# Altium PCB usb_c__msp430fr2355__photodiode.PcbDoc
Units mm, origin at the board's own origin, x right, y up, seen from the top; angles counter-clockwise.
Board outline 56 x 30 mm, 2 copper layers (Top, Bottom), stack 0 mm thick; 27 components, 18 nets, 154 pads, 44 vias.
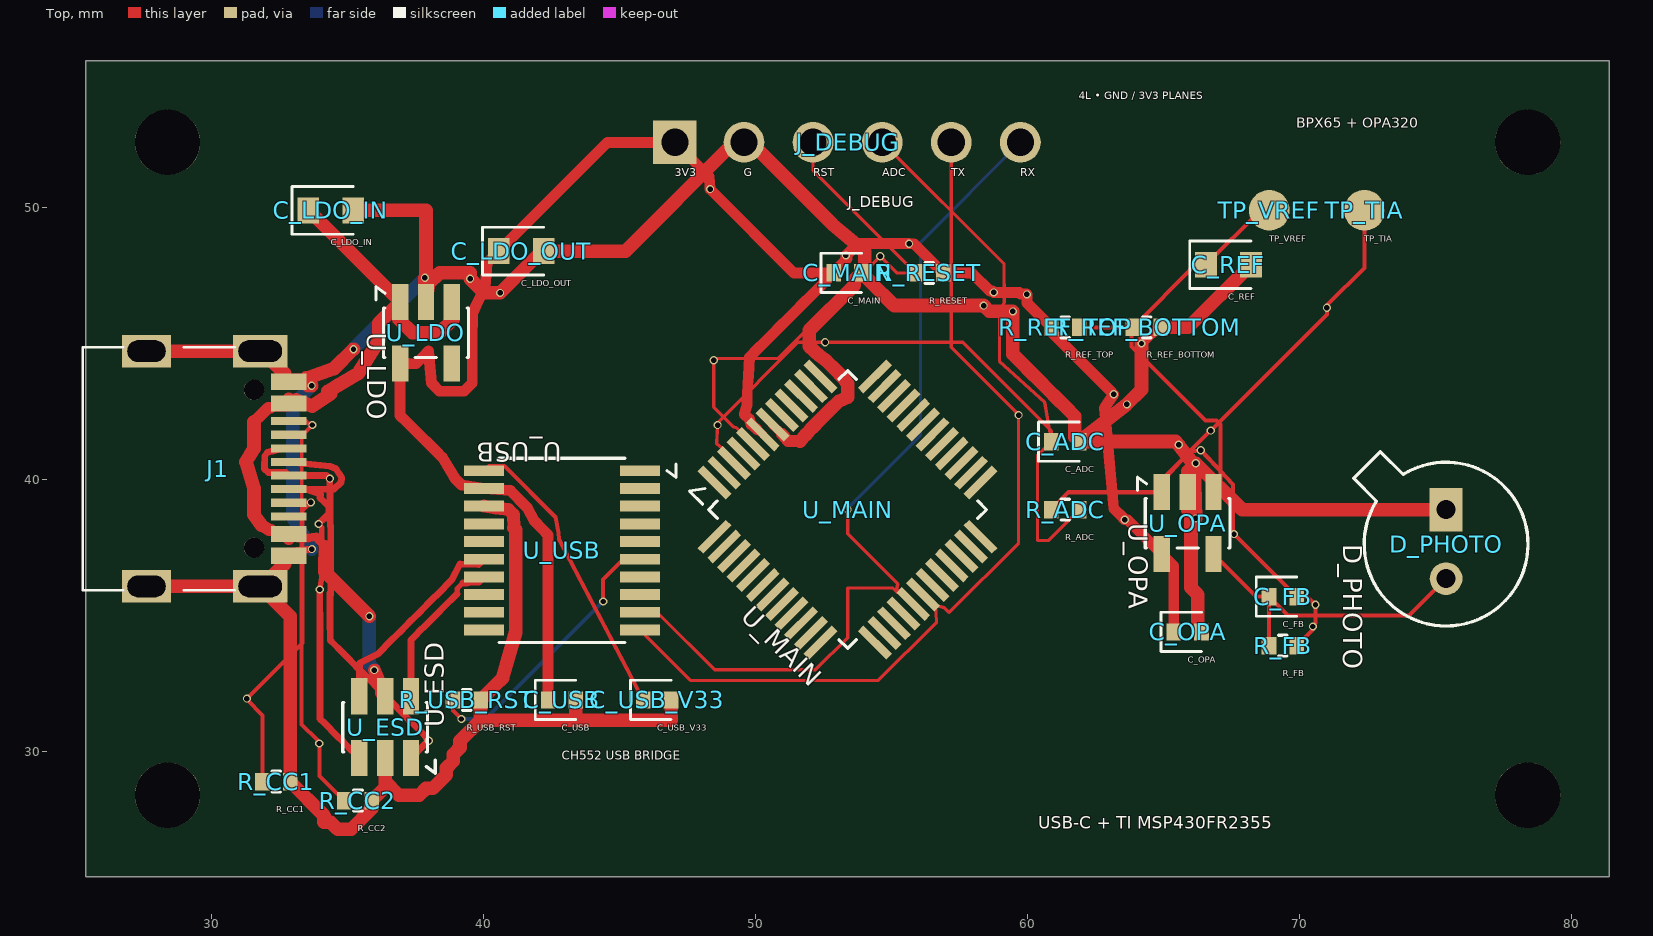
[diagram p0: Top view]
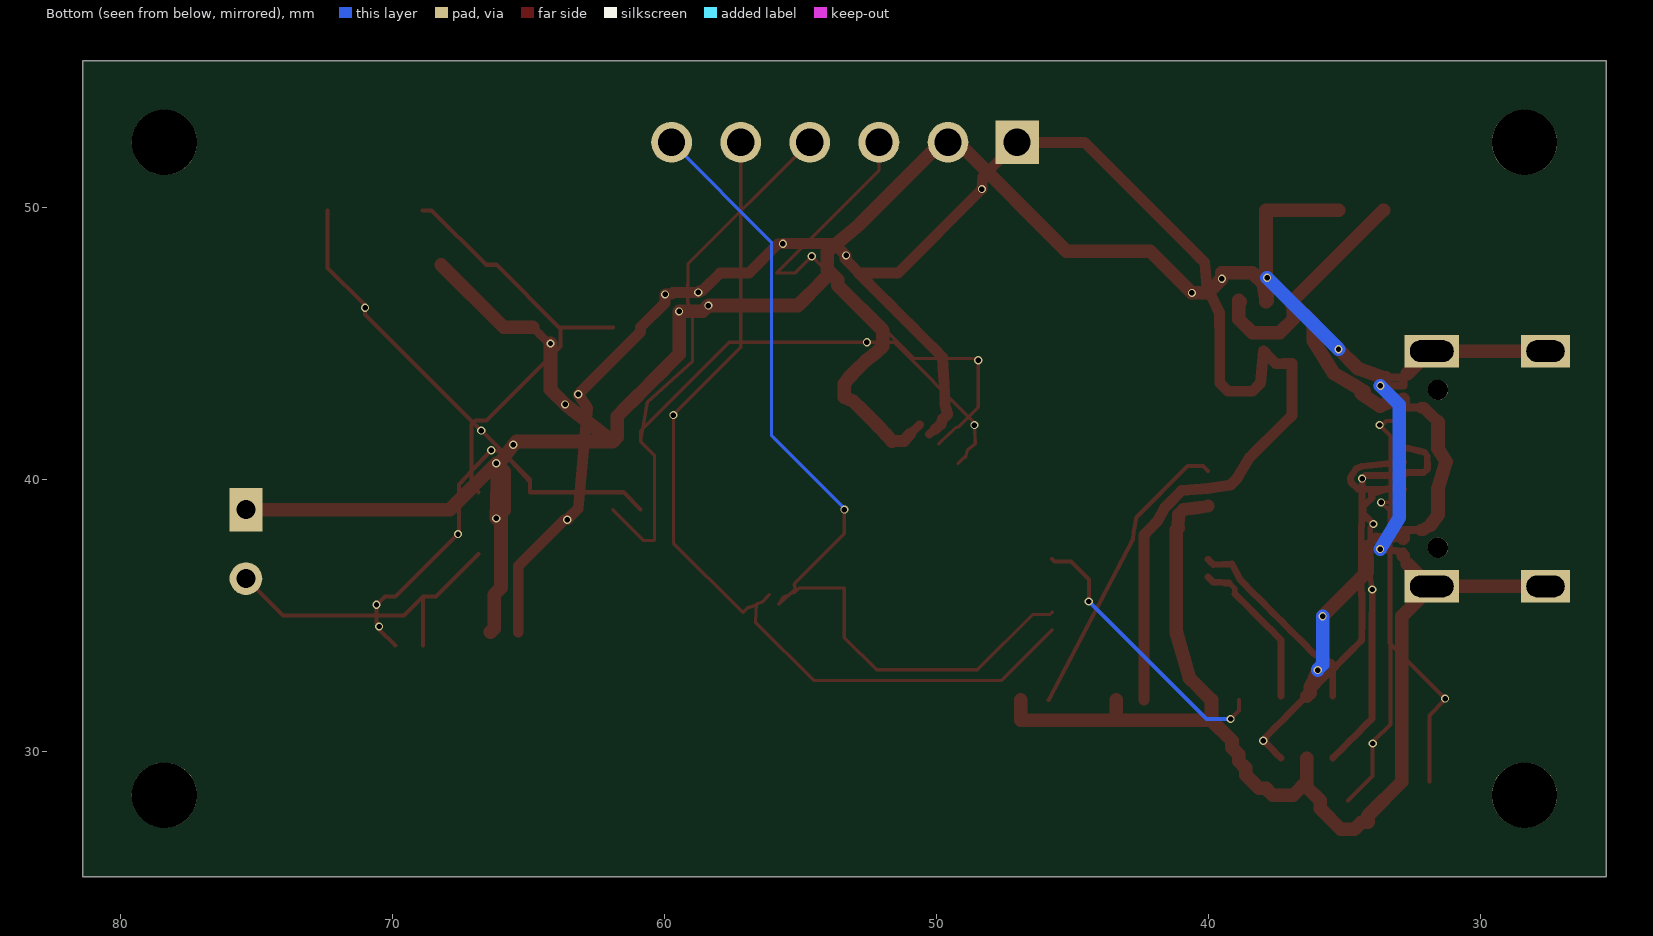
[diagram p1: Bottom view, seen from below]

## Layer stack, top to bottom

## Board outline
25.4,55.4 81.4,55.4 81.4,25.4 25.4,25.4

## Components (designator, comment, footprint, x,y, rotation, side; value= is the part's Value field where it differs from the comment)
C_ADC "" TSCIRCUIT-1.5600x0.6400mm 61.4,41.4 r0 top
C_FB "" TSCIRCUIT-1.5600x0.6400mm 69.4,35.7 r0 top
C_LDO_IN "" TSCIRCUIT-2.4500x0.9500mm 34.4,49.9 r0 top
C_LDO_OUT "" TSCIRCUIT-2.4500x0.9500mm 41.4,48.4 r0 top
C_MAIN "" TSCIRCUIT-1.5600x0.6400mm 53.4,47.6 r0 top
C_OPA "" TSCIRCUIT-1.5600x0.6400mm 65.9,34.4 r0 top
C_REF "" TSCIRCUIT-2.4500x0.9500mm 67.4,47.9 r0 top
C_USB "" TSCIRCUIT-1.5600x0.6400mm 42.9,31.9 r0 top
C_USB_V33 "" TSCIRCUIT-1.5600x0.6400mm 46.4,31.9 r0 top
D_PHOTO "" TSCIRCUIT-1.2000x3.9400mm 75.4,37.73 r270 top
J1 "" TSCIRCUIT-6.7732x9.8502mm 30.113,40.4 r90 top
J_DEBUG "" TSCIRCUIT-14.2000x1.5000mm 53.4,52.4 r0 top
R_ADC "" TSCIRCUIT-1.5600x0.6400mm 61.4,38.9 r0 top
R_CC1 "" TSCIRCUIT-1.5600x0.6400mm 32.4,28.9 r0 top
R_CC2 "" TSCIRCUIT-1.5600x0.6400mm 35.4,28.2 r0 top
R_FB "" TSCIRCUIT-1.5600x0.6400mm 69.4,33.9 r0 top
R_REF_BOTTOM "" TSCIRCUIT-1.5600x0.6400mm 64.4,45.6 r0 top
R_REF_TOP "" TSCIRCUIT-1.5600x0.6400mm 61.4,45.6 r0 top
R_RESET "" TSCIRCUIT-1.5600x0.6400mm 56.4,47.6 r0 top
R_USB_RST "" TSCIRCUIT-1.5600x0.6400mm 39.4,31.9 r0 top
TP_TIA "" TSCIRCUIT-1.5000x1.5000mm 72.4,49.9 r0 top
TP_VREF "" TSCIRCUIT-1.5000x1.5000mm 68.9,49.9 r0 top
U_ESD "" TSCIRCUIT-2.5000x3.6000mm#1 36.4,30.9 r90 top
U_LDO "" TSCIRCUIT-2.5000x3.6000mm#2 37.9,45.4 r270 top
U_MAIN "" TSCIRCUIT-11.0309x11.0309mm 53.4,38.9 r315 top
U_OPA "" TSCIRCUIT-2.5000x3.6000mm#2 65.9,38.4 r270 top
U_USB "" TSCIRCUIT-7.2000x6.2500mm 42.9,37.4 r180 top

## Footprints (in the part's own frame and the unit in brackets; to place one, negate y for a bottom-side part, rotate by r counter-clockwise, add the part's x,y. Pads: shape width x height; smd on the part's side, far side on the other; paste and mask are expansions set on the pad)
TSCIRCUIT-1.2000x3.9400mm [mm]
  rect 1.6x1.2 hole 0.7: 1(-1.17,0)
  round 1.2 hole 0.7: 2(1.37,0)
  silkscreen extent -3.3,-3.4 3.11,3.01
TSCIRCUIT-1.5000x1.5000mm [mm]
  round 1.5 smd: 1(0,0)
TSCIRCUIT-1.5600x0.6400mm [mm]
  rect 0.54x0.64 smd: 1(-0.51,0) 2(0.51,0)
  silkscreen extent -0.98,-0.72 0.51,0.72
TSCIRCUIT-2.4500x0.9500mm [mm]
  rect 0.8x0.95 smd: 1(-0.825,0) 2(0.825,0)
  silkscreen extent -1.43,-0.87 0.82,0.87
TSCIRCUIT-2.5000x3.6000mm#1 [mm]
  rect 1.325x0.6 smd: 1(-1.137,-0.95) 2(-1.137,0) 3(-1.137,0.95) 4(1.138,0.95) 5(1.138,0) 6(1.138,-0.95)
  silkscreen extent -1.69,-1.84 0.91,1.56
TSCIRCUIT-2.5000x3.6000mm#2 [mm]
  rect 1.325x0.6 smd: 1(-1.137,-0.95) 2(-1.137,0) 3(-1.137,0.95) 4(1.138,0.95) 5(1.138,-0.95)
  silkscreen extent -1.69,-1.84 0.91,1.56
TSCIRCUIT-6.7732x9.8502mm [mm]
  rect 0.3x1.3 smd: 1(-3.35,-2.737) 2(-3.05,-2.737) 3(-2.55,-2.737) 4(-2.25,-2.737) 5(-1.75,-2.737) 6(-1.25,-2.737) 7(-0.75,-2.737) 8(-0.25,-2.737) 9(0.25,-2.737) 10(0.75,-2.737) 11(1.25,-2.737) 12(1.75,-2.737) 13(2.55,-2.737) 14(2.25,-2.737) 15(3.35,-2.737) 16(3.05,-2.737)
  rect 1.2x2 hole 0.8 slot 1.6 at 90 deg: 17(-4.325,-1.693) 18(4.325,-1.693)
  rect 1.2x1.8 hole 0.8 slot 1.4 at 90 deg: 19(4.325,2.487) 20(-4.325,2.487)
  round 0.75 hole 0.75 unplated: NPTH-1(-2.9,-1.468) NPTH-2(2.9,-1.468)
  silkscreen extent -4.47,-0.75 4.47,4.83
TSCIRCUIT-7.2000x6.2500mm [mm]
  rect 1.475x0.4 smd: 1(-2.862,-2.925) 2(-2.862,-2.275) 3(-2.862,-1.625) 4(-2.862,-0.975) 5(-2.862,-0.325) 6(-2.862,0.325) 7(-2.862,0.975) 8(-2.862,1.625) 9(-2.862,2.275) 10(-2.862,2.925) 11(2.863,2.925) 12(2.863,2.275) 13(2.863,1.625) 14(2.863,0.975) 15(2.863,0.325) 16(2.863,-0.325) 17(2.863,-0.975) 18(2.863,-1.625) 19(2.863,-2.275) 20(2.863,-2.925)
  silkscreen extent -4.19,-3.39 2.31,3.38
TSCIRCUIT-11.0309x11.0309mm [mm]
  rect 1.475x0.3 smd: 1(-4.162,-2.75) 2(-4.162,-2.25) 3(-4.162,-1.75) 4(-4.162,-1.25) 5(-4.162,-0.75) 6(-4.162,-0.25) 7(-4.162,0.25) 8(-4.162,0.75) 9(-4.162,1.25) 10(-4.162,1.75) 11(-4.162,2.25) 12(-4.162,2.75) 25(4.163,2.75) 26(4.162,2.25) 27(4.163,1.75) 28(4.163,1.25) 29(4.163,0.75) 30(4.162,0.25) 31(4.163,-0.25) 32(4.163,-0.75) 33(4.163,-1.25) 34(4.162,-1.75) 35(4.163,-2.25) 36(4.163,-2.75)
  rect 0.3x1.475 smd: 13(-2.75,4.162) 14(-2.25,4.162) 15(-1.75,4.162) 16(-1.25,4.162) 17(-0.75,4.162) 18(-0.25,4.162) 19(0.25,4.162) 20(0.75,4.162) 21(1.25,4.162) 22(1.75,4.162) 23(2.25,4.162) 24(2.75,4.162) 37(2.75,-4.163) 38(2.25,-4.163) 39(1.75,-4.162) 40(1.25,-4.162) 41(0.75,-4.163) 42(0.25,-4.163) 43(-0.25,-4.162) 44(-0.75,-4.162) 45(-1.25,-4.163) 46(-1.75,-4.163) 47(-2.25,-4.162) 48(-2.75,-4.162)
  silkscreen extent -4.59,-3.63 3.61,3.61
TSCIRCUIT-14.2000x1.5000mm [mm]
  rect 1.6x1.6 hole 1: 1(-6.35,0)
  round 1.5 hole 1: 2(-3.81,0) 3(-1.27,0) 4(1.27,0) 5(3.81,0) 6(6.35,0)

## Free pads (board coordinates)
  round 2.4 hole 2.4 unplated: NPTH-3(28.4,28.4) NPTH-4(78.4,52.4) NPTH-5(78.4,28.4) NPTH-6(28.4,52.4)

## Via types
v1: diameter 0.3, hole 0.2, Top to Bottom, 44 vias

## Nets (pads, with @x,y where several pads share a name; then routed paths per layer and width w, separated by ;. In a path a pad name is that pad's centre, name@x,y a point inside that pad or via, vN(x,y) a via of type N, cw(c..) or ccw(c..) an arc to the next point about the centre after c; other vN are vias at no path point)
ADC_IN: C_ADC.1 J_DEBUG.4 R_ADC.2 U_MAIN.3 | length 36.5
  Top w0.12: U_MAIN.3 48.97,40.846 48.945,40.815 48.873,41.087 48.594,41.312 v1(48.62,42.004) 48.638,42.022 48.638,42.115 51.571,45.048 v1(52.574,45.048) 52.633,45.048 57.633,45.048 60.89,41.791 C_ADC.1 ; J_DEBUG.4 59.15,47.926 59.16,46.52 58.98,46.16 58.98,44.36 60.651,42.837 C_ADC.1 ; R_ADC.2 60.771,37.761 60.382,37.761 60.382,40.892 C_ADC.1
GND: C_ADC.2 C_LDO_IN.2 C_LDO_OUT.2 C_MAIN.2 C_OPA.2 C_REF.2 C_USB.2 C_USB_V33.2 D_PHOTO.1 J1.1 J1.2 J1.15 J1.16 J1.17 J1.18 J1.19 J1.20 J_DEBUG.2 R_CC1.2 R_CC2.2 R_REF_BOTTOM.2 R_USB_RST.2 U_ESD.2 U_LDO.2 U_MAIN.7 U_OPA.2 U_USB.18 | length 150.4
  Top w0.275: J1.1@32.849,37.2 J1.2 33.277,37.399 v1(33.705,37.448) ; J1.16 33.206,43.45 v1@33.563,43.45
  Top w0.288: J1.16 J1.16@32.849,43.6
  Top w0.3: J1.1@32.699,36.9 J1.1 J1.1@32.849,37.2 ; 32.699,43.9 J1.15 ; J1.16@32.849,43.6 J1.15 ; 33.499,43.75 33.412,43.75 33.318,43.75 33.224,43.75 33.13,43.75 33.037,43.75 32.943,43.75 J1.15
  Top w0.312: v1(64.203,45.003) 64.259,45.009 64.363,45.111 64.607,45.355
  Top w0.323: U_MAIN.7 U_MAIN.7@50.985,41.679
  Top w0.325: v1@33.564,43.449 v1@33.563,43.45 ; 64.607,45.355 R_REF_BOTTOM.2@64.852,45.6
  Top w0.45: U_MAIN.7@50.985,41.679 51.213,41.421 51.65,41.421
  Top w0.475: U_USB.18 40.484,38.963 40.931,38.9 41.119,38.713 41.132,38.227
  Top w0.5: J1.20 J1.17 ; J1.19 J1.18 31.874,44.725 32.474,44.125 32.699,43.9 ; J1.1@32.699,36.9 32.474,36.675 31.874,36.075 J1.17 ; 33.499,43.75 33.505,43.75 33.599,43.75 34.522,44.085 35.228,44.791 v1(35.236,44.791) ; v1@33.564,43.449 v1(33.697,43.449) ; C_LDO_IN.2 37.9,49.9 U_LDO.2 ; v1(37.862,47.424) 37.862,46.575 U_LDO.2 ; 41.132,38.227 41.2,38.159 41.2,34.4 40.719,32.709 40.45,32.44 40.18,32.17 R_USB_RST.2 ; C_USB_V33.2 46.91,31.15 43.41,31.15 ; 51.65,41.421 51.869,41.66 52.088,41.9 52.416,42.228 52.744,42.556 53.072,42.884 53.4,43.025 53.4,43.525 53.212,43.775 52.931,44.056 52.65,44.338 52.369,44.556 51.983,44.9 51.983,45.483 53.65,47.15 53.65,47.34 C_MAIN.2 ; v1(64.203,45.003) 64.203,43.305 v1(63.665,42.767) C_ADC.2 ; R_REF_BOTTOM.2@64.852,45.6 R_REF_BOTTOM.2 65.925,45.6 C_REF.2 ; C_OPA.2 66.4,34.4 66.275,34.525 66.275,35.775 66.025,36.025 66.025,39.525 65.912,39.525 U_OPA.2 ; D_PHOTO.1 67.9,38.9 v1(66.2,40.6) 65.9,40.3 U_OPA.2 ; J1.17 32.91,34.971 R_CC1.2 32.91,28.89 34.15,27.65 34.15,27.4 34.4,27.4 34.65,27.15 35.15,27.15 35.9,27.9 35.9,28.19 R_CC2.2 36.4,28.69 U_ESD.2 36.4,28.9 36.9,28.4 37.65,28.4 37.9,28.65 38.15,28.65 38.65,29.15 38.65,29.4 38.9,29.65 38.9,29.9 39.15,30.15 39.15,30.4 39.9,31.15 39.9,31.9 R_USB_RST.2 ; U_LDO.2 38,47.2 38.4,47.6 39.522,47.6 v1(39.522,47.385) 39.572,47.335 39.807,47.1 40.041,46.866 40.334,46.866 v1(40.626,46.866) 42.16,48.4 C_LDO_OUT.2 45.233,48.4 49.067,52.233 49.423,52.233 J_DEBUG.2 49.828,52.4 52.853,49.374 54.025,48.4 54.025,47.715 C_MAIN.2 ; R_USB_RST.2 39.91,31.15 43.41,31.15 ; 43.41,31.15 C_USB.2 43.41,31.15 ; C_MAIN.2 54.21,47.3 54.51,47 54.81,46.7 55.11,46.4 55.546,46.4 55.982,46.4 56.418,46.4 56.854,46.4 57.291,46.4 57.727,46.4 58.163,46.4 58.395,46.4 v1(58.398,46.397) 58.609,46.186 v1(59.475,46.186) 59.475,45.792 59.475,45.398 59.475,45.004 59.475,44.61 59.8,44.285 60.126,43.959 60.451,43.634 60.777,43.308 61.102,42.983 61.427,42.658 61.753,42.332 61.753,41.945 61.753,41.557 C_ADC.2 ; C_ADC.2 62.41,41.4 62.91,41.4 63.41,41.4 63.91,41.4 64.41,41.4 64.91,41.4 65.41,41.4 65.454,41.4 v1(65.574,41.28) 65.574,41.269 66.15,40.525 v1(66.2,38.575) 65.9,38.875 U_OPA.2
  Bottom w0.5: v1(33.697,43.449) 33,42.752 33,38.6 v1(33.705,37.448) ; v1(35.236,44.791) 35.236,44.798 v1(37.862,47.424)
MAIN_RESET: J_DEBUG.3 R_RESET.1 U_MAIN.5 | length 19.3
  Top w0.12: U_MAIN.5 49.319,41.898 49.201,41.943 48.476,42.669 v1(48.476,44.391) 48.541,44.456 48.655,44.456 50.846,44.456 v1(54.599,48.209) 54.63,48.178 55.208,47.6 R_RESET.1 52.13,51.36 J_DEBUG.3
PD_SUM: C_FB.1 D_PHOTO.2 R_FB.1 U_OPA.4 | length 11.9
  Top w0.15: U_OPA.4 68.412,35.7 C_FB.1 ; R_FB.1 C_FB.1 ; D_PHOTO.2 74.04,35 69.6,35 69.59,35 C_FB.1
TIA_OUT: C_FB.2 R_ADC.1 R_FB.2 TP_TIA.1 U_OPA.1 | length 29.5
  Top w0.15: R_ADC.1 61.527,39.538 U_OPA.1 ; R_FB.2 70.506,34.496 v1(70.506,34.6) 70.539,34.633 70.539,34.676 70.6,34.737 v1(70.6,35.4) 70.56,35.44 70.552,35.44 70.292,35.7 C_FB.2 67.611,37.999 v1(67.604,37.999) 67.569,38.034 67.569,39.827 v1(66.383,41.081) 66.075,41.032 65.798,40.844 64.95,39.907 U_OPA.1 ; TP_TIA.1 72.4,47.786 71.066,46.452 71.066,46.363 v1(71.021,46.318) 71.021,46.078 66.773,41.83 v1(66.748,41.805) 64.95,40.007 U_OPA.1
UART_MAIN_RX: J_DEBUG.6 U_MAIN.32 U_USB.9 | length 34.1
  Top w0.12: U_USB.9 45.847,35.041 46.477,35.041 48.51,33.008 52.217,33.008 53.4,34.191 53.4,36.017 55.064,36.017 55.219,35.862 55.226,35.866 55.635,35.682 U_MAIN.32 55.209,35.974 55.244,36.165 53.4,38.01 v1(53.4,38.9)
  Bottom w0.12: v1(53.4,38.9) 53.454,38.954 53.454,39.009 56.081,41.635 56.081,41.67 56.081,48.731 J_DEBUG.6
UART_MAIN_TX: J_DEBUG.5 U_MAIN.31 U_USB.10 | length 34.4
  Top w0.12: U_USB.10 47.621,32.617 47.712,32.617 54.53,32.617 56.602,34.689 56.617,34.704 56.671,34.756 56.631,35.426 56.38,35.516 U_MAIN.31 56.416,35.5 56.602,35.435 56.766,35.343 56.961,35.29 57.123,35.128 57.144,35.128 59.685,37.669 v1(59.685,42.374) 59.69,42.379 57.21,44.859 J_DEBUG.5
USB_BRIDGE_RESET: R_USB_RST.1 U_USB.6 | length 10.3
  Top w0.15: R_USB_RST.1 38.89,31.519 39.151,31.258 39.151,31.249 v1(39.2,31.2) ; v1(44.415,35.52) 44.415,36.333 45.076,36.993 45.681,36.993 U_USB.6
  Bottom w0.15: v1(39.2,31.2) 40.095,31.2 v1@44.411,35.516 ; v1@44.411,35.516 v1(44.415,35.52)
USB_BRIDGE_V33: C_USB_V33.1 U_USB.20 | length 11
  Top w0.15: U_USB.20 40.214,40.501 40.779,40.501 42.652,38.628 42.777,38.06 42.796,37.79 C_USB_V33.1
USB_CC1: J1.6 R_CC1.1 | length 12.3
  Top w0.15: R_CC1.1 31.89,31.333 31.312,31.91 31.312,31.945 v1(31.319,31.952) 33.365,33.999 33.365,38.853 33.366,38.863 v1(33.671,39.163) 32.871,39.172 J1.6
USB_CC2: J1.12 R_CC2.1 | length 15.6
  Top w0.15: J1.12 33.484,42.15 33.565,42.069 33.663,42.069 v1(33.723,42.009) 33.325,41.611 33.325,31.177 33.325,31.004 33.909,30.42 33.909,30.369 v1(33.978,30.3) 33.978,29.112 R_CC2.1
USB_DM_MCU: U_ESD.4 U_USB.15 | length 7.4
  Top w0.25: U_ESD.4 35.45,32.257 35.45,32.476 35.45,32.695 35.45,32.914 35.47,33.254 36.129,33.593 36.298,33.762 36.468,33.932 36.638,34.102 36.807,34.271 36.977,34.441 37.147,34.611 37.317,34.78 37.486,34.95 37.656,35.12 37.826,35.29 37.995,35.459 38.165,35.629 38.335,35.799 38.504,35.968 38.674,36.138 38.844,36.308 39.15,36.9 39.837,36.874 39.937,36.975 U_USB.15
USB_DM_PORT: J1.7 J1.9 U_ESD.3 | length 16.2
  Top w0.188: v1(33.954,38.368) 34.069,38.233 34.069,38.005
  Top w0.2: v1(33.997,35.961) 34.035,36.183 34.073,36.405 34.072,36.633 34.072,36.862 34.071,37.09 34.071,37.319 34.07,37.548 34.07,37.776 34.069,38.005
  Top w0.25: J1.9 34.373,40.49 34.588,40.4 34.697,40.236 34.806,40.072 34.775,39.9 34.525,39.65 34.37,39.642 34.207,39.649 33.981,39.649 33.755,39.65 33.528,39.65 33.302,39.65 33.075,39.65 J1.7 33.058,39.651 33.267,39.653 33.476,39.654 34.025,39.462 34.008,39.331 34.169,39.168 34.33,39.005 34.329,38.877 34.327,38.748 34.152,38.573 33.977,38.398 33.977,38.391 v1(33.954,38.368) ; v1(33.997,35.961) 33.997,35.723 33.998,35.485 33.998,35.248 33.999,35.01 33.999,34.772 34,34.535 34,34.297 34,34.059 34.001,33.821 34.001,33.583 34.002,33.346 34.002,33.108 34.003,32.87 34.003,32.633 34.004,32.395 34.004,32.157 34.005,31.919 34.005,31.681 34.006,31.444 34.006,31.206 34.166,31.046 34.327,30.885 34.487,30.725 34.648,30.564 34.808,30.404 34.969,30.244 35.129,30.083 35.29,29.923 U_ESD.3
USB_DP_MCU: U_ESD.6 U_USB.14 | length 5.8
  Top w0.188: 39.039,35.797 39.05,36 39.15,36.1 39.25,36.2
  Top w0.25: U_ESD.6 37.35,32.268 37.35,32.498 37.35,32.728 37.35,32.958 37.35,33.188 37.35,33.418 37.35,33.648 37.35,33.878 37.35,34.108 37.519,34.277 37.688,34.446 37.857,34.615 38.025,34.784 38.194,34.953 38.363,35.121 38.532,35.29 38.701,35.459 38.87,35.628 39.039,35.797 ; 39.25,36.2 39.411,36.203 39.581,36.224 39.622,36.224 39.836,36.224 39.937,36.324 U_USB.14
USB_DP_PORT: J1.8 J1.10 U_ESD.1 | length 16.2
  Top w0.238: 31.966,40.629 31.966,40.867 32.072,41.002
  Top w0.25: 31.966,40.629 31.966,40.392 32.101,40.258 32.314,40.258 32.528,40.258 32.741,40.258 J1.8 33.081,40.15 33.312,40.15 33.544,40.15 33.776,40.15 34.007,40.15 34.239,40.15 34.317,40.072 v1(34.365,40.04) 34.366,39.793 34.366,39.545 34.367,39.298 34.367,39.05 34.368,38.803 34.368,38.555 34.4,38.15 34.4,35.775 34.374,35.833 34.374,35.586 34.375,35.338 34.376,35.091 34.376,34.843 34.377,34.596 34.377,34.348 34.378,34.101 34.546,33.93 34.715,33.76 34.884,33.59 35.052,33.42 35.221,33.25 35.39,33.079 35.558,32.909 35.727,32.739 35.896,32.569 36.064,32.398 36.233,32.228 36.402,32.058 36.57,31.888 36.739,31.717 36.908,31.547 37.076,31.377 37.245,31.207 37.414,31.037 37.583,30.866 37.751,30.696 37.92,30.526 37.92,30.48 v1(38,30.4) 37.988,30.4 37.828,30.241 37.669,30.081 37.51,29.922 U_ESD.1 ; 32.072,41.002 32.264,41.051 32.457,41.101 32.649,41.15 J1.10
VBUS5: C_LDO_IN.1 J1.3 J1.4 J1.13 J1.14 U_ESD.5 U_LDO.1 U_LDO.3 | length 30
  Top w0.275: J1.3 J1.3@33.194,37.85
  Top w0.3: 32.193,42.65 32.199,42.65 32.287,42.65 32.38,42.65 32.474,42.65 32.568,42.65 32.662,42.65 32.755,42.65 J1.14 J1.14@32.849,42.8 ; J1.4@32.199,38.15 32.287,38.15 32.38,38.15 32.474,38.15 32.568,38.15 32.662,38.15 32.755,38.15 J1.4 J1.3@32.849,38 ; J1.13 32.943,42.95 33.037,42.95 J1.13@33.13,42.95
  Top w0.325: J1.3@33.194,37.85 33.539,37.85 33.869,37.9 34.182,37.552
  Top w0.425: 31.578,42.123 31.839,42.385 32.101,42.646 32.105,42.65 32.193,42.65
  Top w0.45: 31.853,38.322 32.131,38.15 32.193,38.15 J1.4@32.199,38.15 ; 34.182,37.085 34.182,37.552
  Top w0.475: J1.13@33.13,42.95 J1.13@33.421,42.824 ; v1(36,33) U_ESD.5@36.133,32.679
  Top w0.5: 31.578,42.123 31.578,41.635 31.578,41.146 31.275,40.65 31.578,39.68 31.578,39.191 31.578,38.703 31.853,38.322 ; J1.3 J1.3@32.849,38 ; J1.13@32.849,42.8 J1.13@32.849,42.95 ; J1.13@33.421,42.824 33.713,42.697 34.4,43.15 34.292,43.25 34.658,43.466 35.4,43.9 36.158,45.107 36.158,45.745 U_LDO.1 ; C_LDO_IN.1 33.587,49.9 U_LDO.1 ; 34.182,37.085 34.182,36.618 34.51,36.29 34.837,35.963 35.164,35.636 35.492,35.308 v1(35.82,34.98) v1(35.82,34.98) ; U_ESD.5@36.133,32.679 36.267,32.358 36.267,32.171 U_ESD.5 ; U_LDO.3 38.9,46.587 38.9,45.9 38.4,45.4 37.4,45.4 36.9,45.9 36.9,46.4 36.95,46.45 U_LDO.1
  Bottom w0.5: v1(35.82,34.98) 35.82,34.535 35.82,34.09 35.82,33.646 35.82,33.201 35.975,33.046 35.975,33.025 v1(36,33)
VCC_3V3: C_LDO_OUT.1 C_MAIN.1 C_OPA.1 C_USB.1 J_DEBUG.1 R_REF_TOP.1 R_RESET.2 U_LDO.5 U_MAIN.6 U_OPA.5 U_USB.19 | length 71.7
  Top w0.312: U_MAIN.6@50.066,41.85 U_MAIN.6
  Top w0.4: C_USB.1 42.39,32.279 42.39,32.659 42.39,33.038 42.39,33.417 42.39,33.797 42.39,34.176 42.39,34.556 42.39,34.935 42.39,35.314 42.39,35.694 42.39,36.073 42.39,36.452 42.39,36.832 42.39,37.211 42.39,37.591 42.39,37.97 42.147,38.213 41.905,38.455 41.6,39 41,39.6 U_USB.19 39.2,39.8 39,40 38.505,40.807 38.246,41.066 37.986,41.325 37.727,41.584 37.468,41.844 37.209,42.103 36.95,42.362 36.95,42.742 36.95,43.122 36.95,43.502 36.95,43.882 U_LDO.5 37.239,44.262 37.528,44.262 37.761,44.495 37.994,44.727 38.1,43.55 38.4,43.25 39.3,43.25 39.6,43.55 39.6,45.05 39.604,46.117 39.758,46.433 39.913,46.75 40.067,47.067 40.151,47.976 40.363,48.188 C_LDO_OUT.1 44.575,52.4 J_DEBUG.1 48.315,51.135 v1(48.343,50.679) 48.403,50.619 51.422,47.6 C_MAIN.1 ; U_MAIN.6@50.066,41.85 49.852,42.033 49.791,42.226 49.6,42.4 49.707,42.763 49.709,43.134 49.729,43.476 49.75,43.817 49.77,44.158 49.791,44.5 50.072,44.782 50.354,45.063 50.636,45.345 50.918,45.627 51.199,45.909 51.481,46.191 51.763,46.473 52.045,46.754 52.326,47.036 52.608,47.318 C_MAIN.1 ; C_OPA.1 65.39,36.822 U_OPA.5 63.688,38.524 v1(63.585,38.524) 63.518,38.591 63.518,38.605 63.184,38.939 62.845,42.637 v1(63.184,43.138) 63.07,43.252 60.89,45.432 R_REF_TOP.1 59.992,46.498 v1(59.992,46.807) 59.969,46.83 59.76,46.83 59.708,46.882 v1(58.774,46.882) 58.733,46.932 58.633,46.932 57.966,47.6 R_RESET.2 55.839,48.671 v1(55.662,48.671) 55.649,48.684 55.438,48.684 53.777,48.684 v1(53.337,48.244) 53.364,48.215 53.383,48.125 52.89,47.625 C_MAIN.1
VREF_0V5: C_REF.1 R_REF_BOTTOM.1 R_REF_TOP.2 TP_VREF.1 U_OPA.3 | length 16.6
  Top w0.15: R_REF_TOP.2 R_REF_BOTTOM.1 ; U_OPA.3 67.111,39.798 67.111,39.928 67.111,42.02 66.953,42.178 66.554,42.178 63.828,44.897 63.832,45.542 R_REF_BOTTOM.1 ; TP_VREF.1 68.575,49.9 C_REF.1 66.19,47.9 R_REF_BOTTOM.1
pads on no net: J1.5 J1.11 J1.NPTH-1 J1.NPTH-2 U_LDO.4 U_MAIN.1 U_MAIN.2 U_MAIN.4 U_MAIN.8 U_MAIN.9 U_MAIN.10 U_MAIN.11 U_MAIN.12 U_MAIN.13 U_MAIN.14 U_MAIN.15 U_MAIN.16 U_MAIN.17 U_MAIN.18 U_MAIN.19 U_MAIN.20 U_MAIN.21 U_MAIN.22 U_MAIN.23 U_MAIN.24 U_MAIN.25 U_MAIN.26 U_MAIN.27 U_MAIN.28 U_MAIN.29 U_MAIN.30 U_MAIN.33 U_MAIN.34 U_MAIN.35 U_MAIN.36 U_MAIN.37 U_MAIN.38 U_MAIN.39 U_MAIN.40 U_MAIN.41 U_MAIN.42 U_MAIN.43 U_MAIN.44 U_MAIN.45 U_MAIN.46 U_MAIN.47 U_MAIN.48 U_USB.1 U_USB.2 U_USB.3 U_USB.4 U_USB.5 U_USB.7 U_USB.8 U_USB.11 U_USB.12 U_USB.13 U_USB.16 U_USB.17

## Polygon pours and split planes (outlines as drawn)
GND on Mid1 (solid): 81.1,55.1 25.7,55.1 25.7,25.7 81.1,25.7
GND on Mid1 (solid): 34.042,39.017 34.04,39.01 34.003,38.941 33.953,38.88 33.893,38.83 33.824,38.793 33.749,38.77 33.671,38.763 33.6,38.77 33.6,38.55 33.621,38.59 33.671,38.651 33.732,38.701 33.801,38.738 33.876,38.76 33.954,38.768 34.032,38.76 34.043,38.757 34.043,38.802
GND on Mid1 (solid): 33.6,38.186 33.6,35.994 33.604,36.039 33.627,36.114 33.664,36.183 33.714,36.244 33.745,36.27 33.773,36.43 33.772,36.633 33.772,36.861 33.771,37.09 33.771,37.318 33.77,37.547 33.77,37.776 33.776,37.835 33.776,37.836 33.776,38.004 33.776,38.012 33.732,38.035 33.671,38.085 33.621,38.146
VCC_3V3 on Mid2 (solid): 81.1,55.1 25.7,55.1 25.7,25.7 81.1,25.7

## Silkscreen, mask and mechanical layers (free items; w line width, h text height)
Top Overlay:
  text "4L • GND / 3V3 PLANES" at 61.9,53.9 h0.48
  text "BPX65 + OPA320" at 69.9,52.8 h0.65
  text "CH552 USB BRIDGE" at 42.9,29.6 h0.55
  text "USB-C + TI MSP430FR2355" at 60.4,27 h0.78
